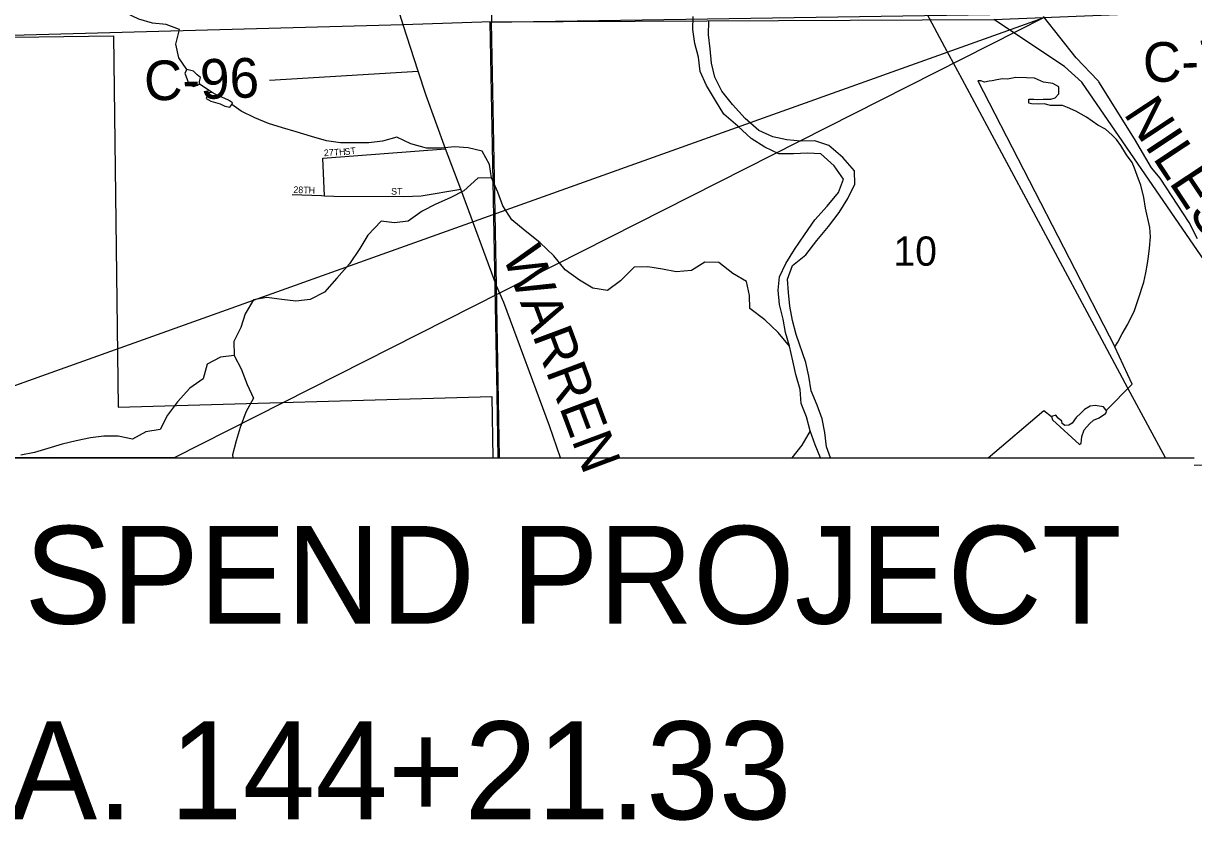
# Model space of a CAD drawing. Extents: x -37878.7 to -37844.7, y -19791.4 to -19769.4.
# Drawn here: x -37875.807 to -37874.132, y -19775.226 to -19774.084 of the extents above; entities that cross this region are included whole.
import ezdxf

# ---------------------------------------------------------------- set-up
doc = ezdxf.new("R2010")
doc.units = 0
for name, color, linetype in [('Default', 7, 'Continuous'), ('GM_X_Corporation', 7, 'Continuous'), ('GM_X_County_Road', 7, 'Continuous'), ('GM_X_County_Road_Text', 7, 'Continuous'), ('GM_X_Major_River', 7, 'Continuous'), ('GM_X_Minor_Lake', 7, 'Continuous'), ('GM_X_Minor_River', 7, 'Continuous'), ('GM_X_Rail_Line', 7, 'Continuous'), ('GM_X_Section', 7, 'Continuous'), ('GM_X_Section_Text', 7, 'Continuous'), ('GM_X_Township', 7, 'Continuous'), ('GM_X_Township_Subdivision', 7, 'Continuous'), ('GM_X_Township_Subdivision_Text', 7, 'Continuous'), ('SH_Data', 7, 'Continuous'), ('TX_P_1', 7, 'Continuous')]:
    doc.layers.add(name, color=color, linetype=linetype)

msp = doc.modelspace()

# ---------------------------------------------------------------- linework, layer by layer
at = {"layer": 'Default'}
msp.add_lwpolyline([(-37875.4547, -19774.1657), (-37875.2421, -19774.1526)], dxfattribs=at)
at = {"layer": 'GM_X_Corporation'}
msp.add_lwpolyline([(-37876.1504, -19774.1098), (-37875.9989, -19774.1065), (-37875.6782, -19774.1024), (-37875.6716, -19774.6338), (-37875.1365, -19774.6186), (-37875.1351, -19774.7063)], dxfattribs=at)
at = {"layer": 'GM_X_County_Road'}
for points in [[(-37875.2635, -19774.0864), (-37875.3367, -19773.8513), (-37875.3643, -19773.7721), (-37875.395, -19773.5859), (-37875.4089, -19773.5107), (-37875.4252, -19773.4239), (-37875.4528, -19773.2532), (-37875.4629, -19773.1964), (-37875.4731, -19773.1386), (-37875.4865, -19773.063), (-37875.4961, -19773.0088), (-37875.5105, -19772.9276), (-37875.5148, -19772.9033)], [(-37875.2635, -19774.0864), (-37875.6312, -19774.0965)], [(-37875.0383, -19774.7063), (-37875.0543, -19774.6607), (-37875.1194, -19774.4839), (-37875.1298, -19774.4599), (-37875.181, -19774.3215), (-37875.2029, -19774.264), (-37875.2304, -19774.1877), (-37875.2421, -19774.1526), (-37875.2635, -19774.0864)], [(-37873.7294, -19775.1112), (-37873.8071, -19774.9241), (-37873.8262, -19774.887), (-37873.9371, -19774.7051), (-37874.1, -19774.4477), (-37874.2922, -19774.1683), (-37874.3166, -19774.1461), (-37874.4179, -19774.0787)], [(-37875.6312, -19774.0965), (-37875.9989, -19774.1065)]]:
    msp.add_lwpolyline(points, dxfattribs=at)
at = {"layer": 'GM_X_Major_River'}
for points in [[(-37874.6661, -19774.7063), (-37874.6738, -19774.6877), (-37874.681, -19774.6677), (-37874.6863, -19774.6477), (-37874.6936, -19774.6285), (-37874.6951, -19774.6085), (-37874.7013, -19774.5873), (-37874.7058, -19774.5677), (-37874.7104, -19774.5466), (-37874.7162, -19774.5269), (-37874.7196, -19774.5077), (-37874.7246, -19774.4869), (-37874.7265, -19774.4664), (-37874.7247, -19774.4474), (-37874.7156, -19774.4282), (-37874.7035, -19774.4082), (-37874.6888, -19774.3871), (-37874.6741, -19774.3655), (-37874.6567, -19774.3461), (-37874.6404, -19774.3264), (-37874.6333, -19774.3073), (-37874.6465, -19774.2882), (-37874.6658, -19774.2712), (-37874.6848, -19774.2704), (-37874.7049, -19774.2713), (-37874.7257, -19774.2713), (-37874.746, -19774.2615), (-37874.7652, -19774.2494), (-37874.7845, -19774.2316), (-37874.8046, -19774.2142), (-37874.8163, -19774.1947), (-37874.8293, -19774.1734), (-37874.8384, -19774.1531), (-37874.8407, -19774.1326), (-37874.8461, -19774.113), (-37874.8488, -19774.0933), (-37874.8484, -19774.0743)], [(-37874.6518, -19774.7063), (-37874.6574, -19774.6908), (-37874.6601, -19774.67), (-37874.6639, -19774.6507), (-37874.6708, -19774.6311), (-37874.6796, -19774.6104), (-37874.6826, -19774.5896), (-37874.6872, -19774.57), (-37874.7009, -19774.53), (-37874.7063, -19774.51), (-37874.7098, -19774.4892), (-37874.7121, -19774.4699), (-37874.7132, -19774.4506), (-37874.7064, -19774.4311), (-37874.6871, -19774.4159), (-37874.6712, -19774.3954), (-37874.6549, -19774.3753), (-37874.6395, -19774.3552), (-37874.627, -19774.3352), (-37874.6168, -19774.3145), (-37874.6176, -19774.2956), (-37874.6343, -19774.2762), (-37874.6544, -19774.2592), (-37874.6742, -19774.2527), (-37874.6943, -19774.2528), (-37874.7144, -19774.251), (-37874.7345, -19774.2468), (-37874.7544, -19774.2378), (-37874.7741, -19774.2204), (-37874.792, -19774.2006), (-37874.8075, -19774.1816), (-37874.8174, -19774.1613), (-37874.8224, -19774.1413), (-37874.8243, -19774.1209), (-37874.8263, -19774.1008), (-37874.8259, -19774.0807)]]:
    msp.add_lwpolyline(points, dxfattribs=at)
at = {"layer": 'GM_X_Minor_Lake'}
for p, q in [((-37875.5759, -19774.1557), (-37875.5727, -19774.1648)), ((-37874.4407, -19774.1665), (-37874.2448, -19774.5475)), ((-37875.5134, -19774.1942), (-37875.5329, -19774.1855)), ((-37874.3339, -19774.6519), (-37874.2953, -19774.6871))]:
    msp.add_line(p, q, dxfattribs=at)
for points in [[(-37875.5727, -19774.1648), (-37875.5703, -19774.1723), (-37875.563, -19774.1748), (-37875.5552, -19774.1716), (-37875.5552, -19774.1674), (-37875.5535, -19774.1617), (-37875.5585, -19774.158), (-37875.5635, -19774.1528), (-37875.5734, -19774.1504), (-37875.5759, -19774.1557)], [(-37874.2448, -19774.5475), (-37874.2404, -19774.5406), (-37874.2342, -19774.5291), (-37874.2262, -19774.5152), (-37874.2168, -19774.4953), (-37874.2111, -19774.4785), (-37874.2032, -19774.4548), (-37874.2005, -19774.4414), (-37874.1981, -19774.4281), (-37874.1964, -19774.4182), (-37874.1952, -19774.4064), (-37874.1936, -19774.39), (-37874.1946, -19774.3764), (-37874.2009, -19774.3488), (-37874.2031, -19774.3337), (-37874.2077, -19774.316), (-37874.2109, -19774.3073), (-37874.2165, -19774.2915), (-37874.2201, -19774.2836), (-37874.2283, -19774.2727), (-37874.2361, -19774.2593), (-37874.2424, -19774.2507), (-37874.2486, -19774.2443), (-37874.2582, -19774.2358), (-37874.2689, -19774.23), (-37874.2855, -19774.2186), (-37874.3008, -19774.2102), (-37874.3123, -19774.2047), (-37874.3195, -19774.2018), (-37874.337, -19774.2018), (-37874.3461, -19774.1994), (-37874.3544, -19774.1999), (-37874.3643, -19774.1994), (-37874.3677, -19774.1987), (-37874.3678, -19774.193), (-37874.3606, -19774.1928), (-37874.3553, -19774.1935), (-37874.3474, -19774.1929), (-37874.3364, -19774.1927), (-37874.3304, -19774.1911), (-37874.3248, -19774.1852), (-37874.325, -19774.175), (-37874.3334, -19774.1706), (-37874.3468, -19774.1683), (-37874.3598, -19774.1628), (-37874.3711, -19774.1623), (-37874.3863, -19774.1619), (-37874.3984, -19774.1644), (-37874.4056, -19774.1638), (-37874.4135, -19774.1651), (-37874.4203, -19774.1668), (-37874.4248, -19774.1669), (-37874.4312, -19774.1686), (-37874.4366, -19774.1668), (-37874.4407, -19774.1665)], [(-37875.5329, -19774.1855), (-37875.5371, -19774.1834), (-37875.5424, -19774.1839), (-37875.5438, -19774.1873), (-37875.5456, -19774.1919), (-37875.5391, -19774.1959), (-37875.5254, -19774.1994), (-37875.5189, -19774.2031), (-37875.5117, -19774.2041), (-37875.5087, -19774.2006), (-37875.508, -19774.1983), (-37875.5134, -19774.1942)], [(-37874.2953, -19774.6871), (-37874.2931, -19774.6852), (-37874.2922, -19774.6757), (-37874.2889, -19774.6665), (-37874.2812, -19774.6576), (-37874.2752, -19774.6526), (-37874.2673, -19774.649), (-37874.258, -19774.6431), (-37874.2562, -19774.6396), (-37874.2608, -19774.6336), (-37874.273, -19774.6316), (-37874.2802, -19774.6325), (-37874.2884, -19774.6373), (-37874.2936, -19774.6423), (-37874.3003, -19774.6489), (-37874.3058, -19774.6566), (-37874.3107, -19774.6598), (-37874.3163, -19774.6603), (-37874.3202, -19774.6573), (-37874.3206, -19774.6539), (-37874.3257, -19774.6495), (-37874.3292, -19774.6454), (-37874.3356, -19774.647), (-37874.3339, -19774.6519)]]:
    msp.add_lwpolyline(points, dxfattribs=at)
at = {"layer": 'GM_X_Minor_River'}
for p, q in [((-37874.2199, -19774.6009), (-37874.2448, -19774.5475)), ((-37874.257, -19774.6385), (-37874.2199, -19774.6009)), ((-37874.426, -19774.7063), (-37874.3464, -19774.6385)), ((-37874.3464, -19774.6385), (-37874.3356, -19774.647))]:
    msp.add_line(p, q, dxfattribs=at)
for points in [[(-37875.5734, -19774.1504), (-37875.5848, -19774.1335), (-37875.5889, -19774.1139), (-37875.5837, -19774.0933), (-37875.6028, -19774.0857), (-37875.6222, -19774.0839), (-37875.642, -19774.0782), (-37875.6611, -19774.0691), (-37875.6755, -19774.0501), (-37875.6775, -19774.0479)], [(-37875.5371, -19774.1834), (-37875.5552, -19774.1716)], [(-37875.1371, -19774.3056), (-37875.1402, -19774.2864), (-37875.1505, -19774.2672), (-37875.1706, -19774.2623), (-37875.19, -19774.2612), (-37875.2093, -19774.2632), (-37875.2301, -19774.2629), (-37875.2526, -19774.2569), (-37875.2725, -19774.2471), (-37875.2932, -19774.2528), (-37875.3125, -19774.2552), (-37875.3337, -19774.2556), (-37875.3534, -19774.2553), (-37875.3735, -19774.2527), (-37875.3949, -19774.2463), (-37875.4166, -19774.2396), (-37875.4364, -19774.2339), (-37875.4562, -19774.2279), (-37875.4757, -19774.2196), (-37875.4956, -19774.2098), (-37875.5087, -19774.2006)], [(-37874.7104, -19774.5466), (-37874.7268, -19774.5268), (-37874.7457, -19774.5086), (-37874.7673, -19774.4927), (-37874.7677, -19774.4738), (-37874.7722, -19774.4541), (-37874.7914, -19774.4424), (-37874.8118, -19774.4265), (-37874.8315, -19774.4262), (-37874.851, -19774.4384), (-37874.8729, -19774.44), (-37874.8923, -19774.4362), (-37874.9132, -19774.4329), (-37874.9329, -19774.4333), (-37874.9522, -19774.4531), (-37874.9712, -19774.4668), (-37874.9922, -19774.4634), (-37875.0113, -19774.4521), (-37875.0317, -19774.437), (-37875.0481, -19774.4172), (-37875.0678, -19774.3979), (-37875.089, -19774.3813), (-37875.1082, -19774.3654), (-37875.1208, -19774.3455), (-37875.128, -19774.3259), (-37875.1371, -19774.3056), (-37875.1565, -19774.3061), (-37875.1765, -19774.3243), (-37875.1964, -19774.3343), (-37875.2167, -19774.343), (-37875.2365, -19774.3533), (-37875.2563, -19774.3674), (-37875.276, -19774.3698), (-37875.295, -19774.3675), (-37875.3142, -19774.3877), (-37875.3256, -19774.4069), (-37875.3403, -19774.4285), (-37875.3584, -19774.449), (-37875.3762, -19774.4691), (-37875.3968, -19774.4798), (-37875.4172, -19774.4821), (-37875.4373, -19774.4799), (-37875.4586, -19774.4769), (-37875.4778, -19774.48), (-37875.4899, -19774.5), (-37875.496, -19774.5199), (-37875.5061, -19774.5398), (-37875.5053, -19774.5599), (-37875.525, -19774.5623), (-37875.5441, -19774.5725), (-37875.5497, -19774.5935), (-37875.5688, -19774.6065), (-37875.5865, -19774.6262), (-37875.6009, -19774.6455), (-37875.6115, -19774.6658), (-37875.6319, -19774.6693), (-37875.651, -19774.6796), (-37875.6715, -19774.6755), (-37875.692, -19774.6752), (-37875.7112, -19774.6779), (-37875.7316, -19774.6821), (-37875.7516, -19774.6867), (-37875.7723, -19774.6932), (-37875.7915, -19774.6986), (-37875.8107, -19774.7024)], [(-37875.5053, -19774.5599), (-37875.4955, -19774.5791), (-37875.4867, -19774.6013), (-37875.4779, -19774.6208), (-37875.4889, -19774.6412), (-37875.4971, -19774.663), (-37875.5028, -19774.6821), (-37875.5077, -19774.7023), (-37875.5073, -19774.7063)], [(-37874.681, -19774.6677), (-37874.6927, -19774.6881), (-37874.7073, -19774.7063)]]:
    msp.add_lwpolyline(points, dxfattribs=at)
at = {"layer": 'GM_X_Rail_Line'}
msp.add_lwpolyline([(-37874.1722, -19774.7063), (-37874.2226, -19774.6129), (-37874.2667, -19774.5309), (-37874.4202, -19774.2443), (-37874.4633, -19774.164), (-37874.4879, -19774.1182), (-37874.521, -19774.0567), (-37874.6066, -19773.8972), (-37874.6432, -19773.8291), (-37874.6648, -19773.7873), (-37874.6871, -19773.7463), (-37874.7008, -19773.7201), (-37874.7105, -19773.7003), (-37874.7204, -19773.6789), (-37874.7396, -19773.6339), (-37874.7573, -19773.5864), (-37874.773, -19773.5422), (-37874.8022, -19773.4615), (-37874.8396, -19773.3566), (-37874.849, -19773.3327), (-37874.8582, -19773.3083), (-37874.8684, -19773.277), (-37874.8892, -19773.2183), (-37874.9297, -19773.106)], dxfattribs=at)
at = {"layer": 'GM_X_Section'}
msp.add_lwpolyline([(-37875.1274, -19774.7063), (-37875.1291, -19774.6153), (-37875.1389, -19774.0828), (-37873.8639, -19774.0628), (-37873.7756, -19774.0615), (-37873.7599, -19774.7127), (-37874.0664, -19774.7168), (-37874.131, -19774.7175)], dxfattribs=at)
at = {"layer": 'GM_X_Township'}
for points in [[(-37875.2046, -19770.3854), (-37875.2045, -19770.3883), (-37875.1996, -19770.7262), (-37875.1932, -19770.9906), (-37875.1922, -19771.0645), (-37875.1913, -19771.1313), (-37875.1903, -19771.2032), (-37875.1894, -19771.2701), (-37875.1885, -19771.3343), (-37875.1874, -19771.4123), (-37875.1857, -19771.5367), (-37875.1848, -19771.6035), (-37875.1845, -19771.6245), (-37875.184, -19771.6631), (-37875.1834, -19771.7048), (-37875.1821, -19771.8044), (-37875.1759, -19771.948), (-37875.1648, -19772.4986), (-37875.1373, -19774.0823), (-37875.2635, -19774.0864), (-37875.9989, -19774.1065), (-37876.1504, -19774.1098)], [(-37875.1256, -19774.7063), (-37875.1298, -19774.4599), (-37875.1323, -19774.3303), (-37875.1373, -19774.0823), (-37874.4179, -19774.0787), (-37874.0166, -19774.0627), (-37873.9068, -19774.0689), (-37873.8209, -19774.0673), (-37873.7613, -19774.0661), (-37873.4895, -19774.0538), (-37873.4391, -19774.0538), (-37873.321, -19774.051), (-37873.2959, -19774.0514), (-37873.2256, -19774.0503), (-37873.087, -19774.0476), (-37873.0701, -19774.0483), (-37872.9424, -19774.0456), (-37872.8551, -19774.043), (-37872.7641, -19774.0427), (-37872.3802, -19774.036), (-37872.2676, -19774.0341)]]:
    msp.add_lwpolyline(points, dxfattribs=at)
at = {"layer": 'GM_X_Township_Subdivision'}
for points in [[(-37875.3784, -19774.2774), (-37875.2029, -19774.264)], [(-37875.3762, -19774.3311), (-37875.3784, -19774.2774)], [(-37875.4226, -19774.3295), (-37875.3804, -19774.3309), (-37875.3762, -19774.3311), (-37875.363, -19774.3316), (-37875.2627, -19774.332), (-37875.2376, -19774.3312), (-37875.181, -19774.3215)]]:
    msp.add_lwpolyline(points, dxfattribs=at)
at = {"layer": 'SH_Data'}
for p, q in [((-37874.3, -19774.1335), (-37874.3467, -19774.0745)), ((-37874.2691, -19774.166), (-37874.3, -19774.1335)), ((-37874.2166, -19774.2495), (-37874.2677, -19774.1678)), ((-37874.1921, -19774.2912), (-37874.2166, -19774.2495)), ((-37874.1798, -19774.3058), (-37874.1921, -19774.2912)), ((-37874.1382, -19774.3696), (-37874.1798, -19774.3058)), ((-37874.1266, -19774.3928), (-37874.1382, -19774.3696))]:
    msp.add_line(p, q, dxfattribs=at)
msp.add_arc((-37874.2773, -19774.1738), 0.0113, 32.0405, 43.5621, dxfattribs=at)
at = {"layer": 'TX_P_1'}
msp.add_line((-37876.1098, -19774.7063), (-37874.131, -19774.7063), dxfattribs=at)
msp.add_lwpolyline([(-37876.1098, -19774.7063), (-37874.3457, -19774.0758), (-37875.5914, -19774.7063)], dxfattribs=at)
msp.add_lwpolyline([(-37876.1098, -19774.7063), (-37874.3457, -19774.0758), (-37875.5914, -19774.7063)], close=True, dxfattribs=at)

# ---------------------------------------------------------------- texts
at = {"layer": 'GM_X_County_Road_Text'}
for s, height, rotation, p in [('C-78', 0.05682, 2.4002, (-37874.2034, -19774.1692)), ('C-96', 0.05682, 1.6997, (-37875.6337, -19774.1951)), ('NILES-WARREN', 0.056818, 303.4615, (-37874.2333, -19774.2135)), ('WARREN', 0.05682, 290.4851, (-37875.1218, -19774.4162))]:
    msp.add_text(s, height=height, rotation=rotation, dxfattribs=at).set_placement(p)
at = {"layer": 'GM_X_Section_Text'}
msp.add_text('10', height=0.04186, rotation=0, dxfattribs=at).set_placement((-37874.5617, -19774.4313))
at = {"layer": 'GM_X_Township_Subdivision_Text'}
for s, rotation, p in [('ST', 7.1284, (-37875.3469, -19774.2729)), ('27TH', 3.5746, (-37875.3768, -19774.2746)), ('28TH', 358.2112, (-37875.4208, -19774.3271)), ('ST', 0, (-37875.2808, -19774.3296))]:
    msp.add_text(s, height=0.00947, rotation=rotation, dxfattribs=at).set_placement(p)
at = {"layer": 'TX_P_1'}
for s, p in [('SUSPEND PROJECT', (-37876.0658, -19774.9439)), ('STA. 144+21.33', (-37876.0658, -19775.2239))]:
    msp.add_text(s, height=0.14, rotation=360, dxfattribs=at).set_placement(p)

doc.saveas('drawing.dxf')
